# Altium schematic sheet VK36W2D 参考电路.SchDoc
size A4
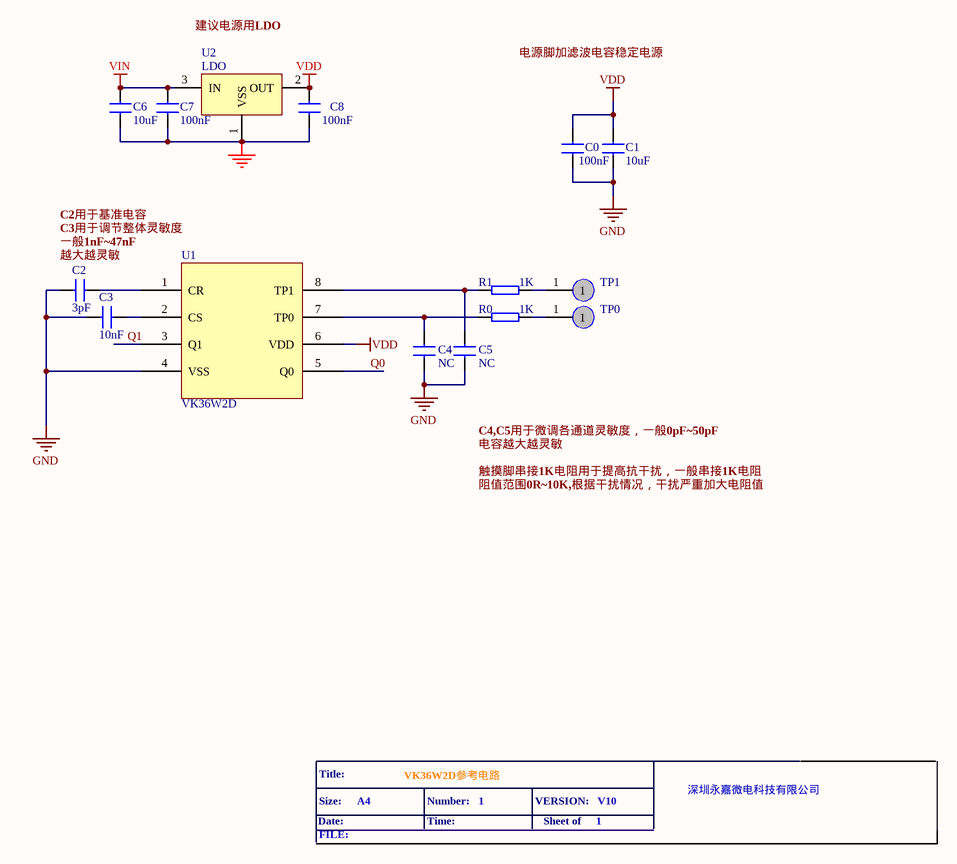
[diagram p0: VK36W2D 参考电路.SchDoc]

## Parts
C0  100nF  [0603-C]
C1  10uF  [0603-C]
C2  value 3pF  [0603-C]  (hidden comment: 10uF)
C3  value 10nF  [0603-C]  (hidden comment: 10uF)
C4  value NC  [0603-C]  (hidden comment: 10uF)
C5  value NC  [0603-C]  (hidden comment: 10uF)
C6  10uF  [0805-C]
C7  100nF  [0805-C]
C8  100nF  [0805-C]
R0  1K  [0603-R]
R1  1K  [0603-R]
TP0  TPAD  [TP-PAD0]  (value not drawn)
TP1  TPAD  [TP-PAD0]  (value not drawn)
U1  VK36W2D
U2  LDO  [SOT-23]

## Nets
GND: C0.2 C1.2 C2.2 C3.2 C4.1 C5.1 C6.2 C7.2 C8.2 U1.4(VSS) U2.1(VSS)
VDD: C0.1 C1.1 C8.1 U1.6(VDD) U2.2(OUT)
VIN: C6.1 C7.1 U2.3(IN)
Q0: U1.5(Q0)
Q1: U1.3(Q1)
NetC2_1: C2.1 U1.1(CR)
NetC3_1: C3.1 U1.2(CS)
NetC4_2: C4.2 R0.2 U1.7(TP0)
NetC5_2: C5.2 R1.2 U1.8(TP1)
NetR0_1: R0.1 TP0.1
NetR1_1: R1.1 TP1.1

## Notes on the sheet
- 建议电源用LDO
- 电源脚加滤波电容稳定电源
- C2用于基准电容
- C3用于调节整体灵敏度
- (near C2) 一般1nF~47nF
- (near C2) 越大越灵敏
- 触摸脚串接1K电阻用于提高抗干扰，一般串接1K电阻
- 阻值范围0R
  0K,根据干扰情况，干扰严重加大电阻值
- C4,C5用于微调各通道灵敏度，一般0pF~50pF
- 电容越大越灵敏
- Date:
- Title:
- Size:
- A4
- VK36W2D参考电路
- Number:
- Time:
- 1
- VERSION:
- Sheet of
- V10
- 深圳永嘉微电科技有限公司
- FILE:

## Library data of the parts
C0-C8 = CAP: Capacitor
R0 R1 = RES: Resistor
TP0 TP1 = TPAD: TESTING
U2 = V6206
